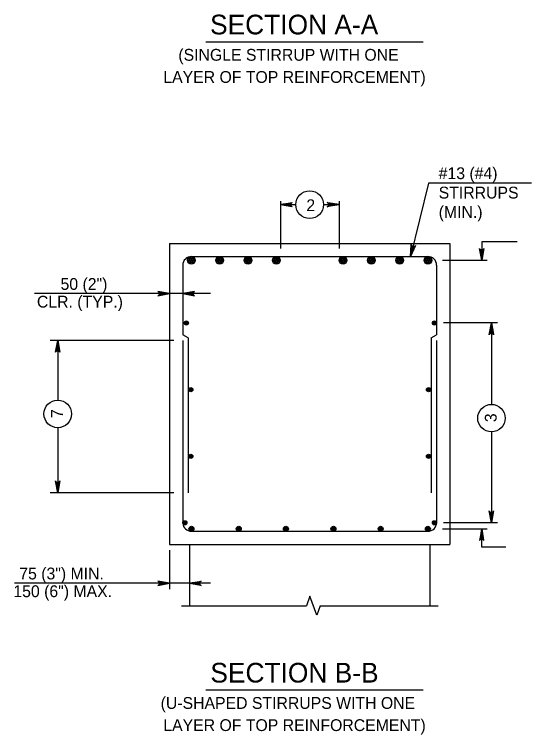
# Model space of a CAD drawing. Extents: x 646165 to 651486, y 296916 to 299292.
# Drawn here: x 647939.7 to 648071, y 298263.1 to 298446.1 of the extents above; entities that cross this region are included whole.
import ezdxf

# ---------------------------------------------------------------- set-up
doc = ezdxf.new("R2010")
doc.units = 0
for name, color, linetype in [('51', 7, 'Continuous'), ('52', 7, 'Continuous'), ('53', 7, 'Continuous'), ('54', 7, 'Continuous')]:
    doc.layers.add(name, color=color, linetype=linetype)

msp = doc.modelspace()

# ---------------------------------------------------------------- linework, layer by layer
at = {"layer": '51'}
for p, q in [((647979.08, 298387.9), (647979.08, 298311.43)), ((647979.08, 298387.9), (648050.2, 298387.9)), ((648050.2, 298387.9), (648050.2, 298311.43)), ((647979.08, 298311.43), (648050.2, 298311.43)), ((647984.08, 298311.43), (647984.08, 298295.85)), ((648045.2, 298311.43), (648045.2, 298295.85))]:
    msp.add_line(p, q, dxfattribs=at)
at = {"layer": '52'}
for p, q in [((648044.79, 298403.22), (648040.28, 298384.57)), ((648071.01, 298403.22), (648044.79, 298403.22)), ((648007.21, 298398.59), (648007.21, 298386.58)), ((648022.1, 298398.59), (648022.1, 298386.58)), ((648007.21, 298397.74), (648011.14, 298397.74)), ((648018.14, 298397.74), (648022.1, 298397.74)), ((648067.31, 298388.27), (648058.35, 298388.27)), ((648058.35, 298388.27), (648058.35, 298383.6)), ((648048.39, 298383.6), (648059.68, 298383.6)), ((647989.47, 298375.15), (647944.78, 298375.15)), ((648062.36, 298367.68), (648048.63, 298367.68)), ((648060.81, 298367.68), (648060.81, 298347.01)), ((647980.12, 298363.23), (647948.71, 298363.23)), ((647950.65, 298363.23), (647950.65, 298348.07)), ((647950.65, 298341.07), (647950.65, 298324.57)), ((648060.81, 298340.01), (648060.81, 298316.93)), ((647980.12, 298324.57), (647948.71, 298324.57)), ((648062.36, 298316.93), (648048.63, 298316.93)), ((648048.39, 298315.4), (648059.68, 298315.4)), ((648058.35, 298310.73), (648058.35, 298315.4)), ((648064.49, 298310.73), (648058.35, 298310.73)), ((647979.08, 298309.95), (647979.08, 298300.07)), ((647989.47, 298301.55), (647939.65, 298301.55)), ((647982.11, 298295.85), (648013.8, 298295.85)), ((648017.3, 298295.85), (648047.27, 298295.85))]:
    msp.add_line(p, q, dxfattribs=at)
for points in [[(648007.21, 298397.74), (648010.19, 298398.3), (648010.08, 298398.22), (648009.96, 298398.14), (648009.9, 298398.04), (648009.84, 298397.94), (648009.82, 298397.84), (648009.81, 298397.74), (648009.82, 298397.64), (648009.84, 298397.54), (648009.9, 298397.44), (648009.96, 298397.34), (648010.08, 298397.26), (648010.19, 298397.18), (648007.21, 298397.74), (648010.08, 298397.26), (648009.96, 298397.34), (648007.21, 298397.74), (648009.9, 298397.44), (648009.84, 298397.54), (648007.21, 298397.74), (648009.82, 298397.64), (648009.81, 298397.74), (648007.21, 298397.74), (648009.82, 298397.84), (648009.84, 298397.94), (648007.21, 298397.74), (648009.9, 298398.04), (648009.96, 298398.14), (648007.21, 298397.74), (648010.08, 298398.22)], [(648022.1, 298397.74), (648019.12, 298397.18), (648019.23, 298397.26), (648019.35, 298397.34), (648019.41, 298397.44), (648019.46, 298397.54), (648019.48, 298397.64), (648019.5, 298397.74), (648019.48, 298397.84), (648019.46, 298397.94), (648019.41, 298398.04), (648019.35, 298398.14), (648019.23, 298398.22), (648019.12, 298398.3), (648022.1, 298397.74), (648019.23, 298398.22), (648019.35, 298398.14), (648022.1, 298397.74), (648019.41, 298398.04), (648019.46, 298397.94), (648022.1, 298397.74), (648019.48, 298397.84), (648019.5, 298397.74), (648022.1, 298397.74), (648019.48, 298397.64), (648019.46, 298397.54), (648022.1, 298397.74), (648019.41, 298397.44), (648019.35, 298397.34), (648022.1, 298397.74), (648019.23, 298397.26)], [(648040.28, 298384.57), (648040.44, 298387.6), (648040.49, 298387.47), (648040.54, 298387.34), (648040.62, 298387.26), (648040.7, 298387.17), (648040.8, 298387.13), (648040.89, 298387.09), (648040.99, 298387.09), (648041.09, 298387.08), (648041.2, 298387.11), (648041.31, 298387.15), (648041.42, 298387.24), (648041.52, 298387.33), (648040.28, 298384.57), (648041.42, 298387.24), (648041.31, 298387.15), (648040.28, 298384.57), (648041.2, 298387.11), (648041.09, 298387.08), (648040.28, 298384.57), (648040.99, 298387.09), (648040.89, 298387.09), (648040.28, 298384.57), (648040.8, 298387.13), (648040.7, 298387.17), (648040.28, 298384.57), (648040.62, 298387.26), (648040.54, 298387.34), (648040.28, 298384.57), (648040.49, 298387.47)], [(648058.35, 298383.6), (648057.79, 298386.58), (648057.87, 298386.47), (648057.95, 298386.35), (648058.05, 298386.29), (648058.15, 298386.23), (648058.25, 298386.22), (648058.35, 298386.2), (648058.45, 298386.22), (648058.55, 298386.23), (648058.65, 298386.29), (648058.75, 298386.35), (648058.83, 298386.47), (648058.91, 298386.58), (648058.35, 298383.6), (648058.83, 298386.47), (648058.75, 298386.35), (648058.35, 298383.6), (648058.65, 298386.29), (648058.55, 298386.23), (648058.35, 298383.6), (648058.45, 298386.22), (648058.35, 298386.2), (648058.35, 298383.6), (648058.25, 298386.22), (648058.15, 298386.23), (648058.35, 298383.6), (648058.05, 298386.29), (648057.95, 298386.35), (648058.35, 298383.6), (648057.87, 298386.47)], [(647979.08, 298375.15), (647976.1, 298375.71), (647976.21, 298375.63), (647976.33, 298375.55), (647976.39, 298375.45), (647976.45, 298375.35), (647976.47, 298375.25), (647976.48, 298375.15), (647976.47, 298375.05), (647976.45, 298374.95), (647976.39, 298374.85), (647976.33, 298374.75), (647976.21, 298374.68), (647976.1, 298374.6), (647979.08, 298375.15), (647976.21, 298374.68), (647976.33, 298374.75), (647979.08, 298375.15), (647976.39, 298374.85), (647976.45, 298374.95), (647979.08, 298375.15), (647976.47, 298375.05), (647976.48, 298375.15), (647979.08, 298375.15), (647976.47, 298375.25), (647976.45, 298375.35), (647979.08, 298375.15), (647976.39, 298375.45), (647976.33, 298375.55), (647979.08, 298375.15), (647976.21, 298375.63)], [(647982.42, 298375.15), (647985.4, 298374.6), (647985.28, 298374.68), (647985.17, 298374.75), (647985.11, 298374.85), (647985.05, 298374.95), (647985.03, 298375.05), (647985.02, 298375.15), (647985.03, 298375.25), (647985.05, 298375.35), (647985.11, 298375.45), (647985.17, 298375.55), (647985.28, 298375.63), (647985.4, 298375.71), (647982.42, 298375.15), (647985.28, 298375.63), (647985.17, 298375.55), (647982.42, 298375.15), (647985.11, 298375.45), (647985.05, 298375.35), (647982.42, 298375.15), (647985.03, 298375.25), (647985.02, 298375.15), (647982.42, 298375.15), (647985.03, 298375.05), (647985.05, 298374.95), (647982.42, 298375.15), (647985.11, 298374.85), (647985.17, 298374.75), (647982.42, 298375.15), (647985.28, 298374.68)], [(648060.81, 298367.68), (648061.37, 298364.7), (648061.29, 298364.81), (648061.21, 298364.93), (648061.11, 298364.99), (648061.01, 298365.05), (648060.91, 298365.06), (648060.81, 298365.08), (648060.71, 298365.06), (648060.61, 298365.05), (648060.51, 298364.99), (648060.41, 298364.93), (648060.33, 298364.81), (648060.25, 298364.7), (648060.81, 298367.68), (648060.33, 298364.81), (648060.41, 298364.93), (648060.81, 298367.68), (648060.51, 298364.99), (648060.61, 298365.05), (648060.81, 298367.68), (648060.71, 298365.06), (648060.81, 298365.08), (648060.81, 298367.68), (648060.91, 298365.06), (648061.01, 298365.05), (648060.81, 298367.68), (648061.11, 298364.99), (648061.21, 298364.93), (648060.81, 298367.68), (648061.29, 298364.81)], [(647950.65, 298363.23), (647951.21, 298360.25), (647951.13, 298360.37), (647951.05, 298360.48), (647950.95, 298360.54), (647950.85, 298360.6), (647950.75, 298360.62), (647950.65, 298360.63), (647950.55, 298360.62), (647950.45, 298360.6), (647950.35, 298360.54), (647950.25, 298360.48), (647950.17, 298360.37), (647950.09, 298360.25), (647950.65, 298363.23), (647950.17, 298360.37), (647950.25, 298360.48), (647950.65, 298363.23), (647950.35, 298360.54), (647950.45, 298360.6), (647950.65, 298363.23), (647950.55, 298360.62), (647950.65, 298360.63), (647950.65, 298363.23), (647950.75, 298360.62), (647950.85, 298360.6), (647950.65, 298363.23), (647950.95, 298360.54), (647951.05, 298360.48), (647950.65, 298363.23), (647951.13, 298360.37)], [(647950.65, 298324.57), (647950.09, 298327.55), (647950.17, 298327.43), (647950.25, 298327.32), (647950.35, 298327.26), (647950.45, 298327.2), (647950.55, 298327.18), (647950.65, 298327.17), (647950.75, 298327.18), (647950.85, 298327.2), (647950.95, 298327.26), (647951.05, 298327.32), (647951.13, 298327.43), (647951.21, 298327.55), (647950.65, 298324.57), (647951.13, 298327.43), (647951.05, 298327.32), (647950.65, 298324.57), (647950.95, 298327.26), (647950.85, 298327.2), (647950.65, 298324.57), (647950.75, 298327.18), (647950.65, 298327.17), (647950.65, 298324.57), (647950.55, 298327.18), (647950.45, 298327.2), (647950.65, 298324.57), (647950.35, 298327.26), (647950.25, 298327.32), (647950.65, 298324.57), (647950.17, 298327.43)], [(648060.81, 298316.93), (648060.25, 298319.92), (648060.33, 298319.8), (648060.41, 298319.69), (648060.51, 298319.63), (648060.61, 298319.57), (648060.71, 298319.55), (648060.81, 298319.53), (648060.91, 298319.55), (648061.01, 298319.57), (648061.11, 298319.63), (648061.21, 298319.69), (648061.29, 298319.8), (648061.37, 298319.92), (648060.81, 298316.93), (648061.29, 298319.8), (648061.21, 298319.69), (648060.81, 298316.93), (648061.11, 298319.63), (648061.01, 298319.57), (648060.81, 298316.93), (648060.91, 298319.55), (648060.81, 298319.53), (648060.81, 298316.93), (648060.71, 298319.55), (648060.61, 298319.57), (648060.81, 298316.93), (648060.51, 298319.63), (648060.41, 298319.69), (648060.81, 298316.93), (648060.33, 298319.8)], [(648058.35, 298315.4), (648057.79, 298312.42), (648057.87, 298312.53), (648057.95, 298312.65), (648058.05, 298312.71), (648058.15, 298312.77), (648058.25, 298312.78), (648058.35, 298312.8), (648058.45, 298312.78), (648058.55, 298312.77), (648058.65, 298312.71), (648058.75, 298312.65), (648058.83, 298312.53), (648058.91, 298312.42), (648058.35, 298315.4), (648058.83, 298312.53), (648058.75, 298312.65), (648058.35, 298315.4), (648058.65, 298312.71), (648058.55, 298312.77), (648058.35, 298315.4), (648058.45, 298312.78), (648058.35, 298312.8), (648058.35, 298315.4), (648058.25, 298312.78), (648058.15, 298312.77), (648058.35, 298315.4), (648058.05, 298312.71), (648057.95, 298312.65), (648058.35, 298315.4), (648057.87, 298312.53)], [(647979.08, 298301.55), (647976.1, 298302.11), (647976.21, 298302.03), (647976.33, 298301.95), (647976.39, 298301.85), (647976.45, 298301.75), (647976.47, 298301.65), (647976.48, 298301.55), (647976.47, 298301.45), (647976.45, 298301.35), (647976.39, 298301.25), (647976.33, 298301.15), (647976.21, 298301.07), (647976.1, 298300.99), (647979.08, 298301.55), (647976.21, 298301.07), (647976.33, 298301.15), (647979.08, 298301.55), (647976.39, 298301.25), (647976.45, 298301.35), (647979.08, 298301.55), (647976.47, 298301.45), (647976.48, 298301.55), (647979.08, 298301.55), (647976.47, 298301.65), (647976.45, 298301.75), (647979.08, 298301.55), (647976.39, 298301.85), (647976.33, 298301.95), (647979.08, 298301.55), (647976.21, 298302.03)], [(647984.08, 298301.55), (647987.07, 298302.11), (647986.95, 298302.03), (647986.84, 298301.95), (647986.78, 298301.85), (647986.72, 298301.75), (647986.7, 298301.65), (647986.68, 298301.55), (647986.7, 298301.45), (647986.72, 298301.35), (647986.78, 298301.25), (647986.84, 298301.15), (647986.95, 298301.07), (647987.07, 298300.99), (647984.08, 298301.55), (647986.95, 298301.07), (647986.84, 298301.15), (647984.08, 298301.55), (647986.78, 298301.25), (647986.72, 298301.35), (647984.08, 298301.55), (647986.7, 298301.45), (647986.68, 298301.55), (647984.08, 298301.55), (647986.7, 298301.65), (647986.72, 298301.75), (647984.08, 298301.55), (647986.78, 298301.85), (647986.84, 298301.95), (647984.08, 298301.55), (647986.95, 298302.03)], [(648017.3, 298295.85), (648016.43, 298293.45), (648014.68, 298298.25), (648013.8, 298295.85)]]:
    msp.add_lwpolyline(points, dxfattribs=at)
for centre in [(648014.64, 298397.74), (647950.65, 298344.57), (648060.81, 298343.51)]:
    msp.add_circle(centre, 3.5, dxfattribs=at)
at = {"layer": '53'}
for p, q in [((647988.25, 298439.14), (648043.46, 298439.14)), ((647988.25, 298274.49), (648043.46, 298274.49))]:
    msp.add_line(p, q, dxfattribs=at)
at = {"layer": '54'}
for p, q in [((647984.62, 298384.57), (648044.67, 298384.57)), ((647982.42, 298382.37), (647982.42, 298364.67)), ((648046.87, 298382.37), (648046.87, 298364.67)), ((647983.75, 298363.9), (647982.42, 298364.67)), ((647983.75, 298363.9), (647983.75, 298324.57)), ((648045.54, 298363.9), (648046.87, 298364.67)), ((648045.54, 298363.9), (648045.54, 298324.57)), ((647982.42, 298363.23), (647982.42, 298316.83)), ((648046.87, 298363.23), (648046.87, 298316.97)), ((647984.62, 298314.77), (648044.67, 298314.77))]:
    msp.add_line(p, q, dxfattribs=at)
for centre, radius in [((647984.62, 298383.6), 0.967), ((647984.62, 298383.6), 0.725), ((647984.62, 298383.6), 0.483), ((647984.62, 298383.6), 0.242), ((647991.78, 298383.6), 0.967), ((647991.78, 298383.6), 0.725), ((647991.78, 298383.6), 0.483), ((647991.78, 298383.6), 0.242), ((647998.98, 298383.6), 0.967), ((647998.98, 298383.6), 0.725), ((647998.98, 298383.6), 0.483), ((647998.98, 298383.6), 0.242), ((648006.18, 298383.6), 0.967), ((648006.18, 298383.6), 0.725), ((648006.18, 298383.6), 0.483), ((648006.18, 298383.6), 0.242), ((648023.11, 298383.6), 0.967), ((648023.11, 298383.6), 0.725), ((648023.11, 298383.6), 0.483), ((648023.11, 298383.6), 0.242), ((648030.31, 298383.6), 0.967), ((648030.31, 298383.6), 0.725), ((648030.31, 298383.6), 0.483), ((648030.31, 298383.6), 0.242), ((648037.51, 298383.6), 0.967), ((648037.51, 298383.6), 0.725), ((648037.51, 298383.6), 0.483), ((648037.51, 298383.6), 0.242), ((648044.67, 298383.6), 0.967), ((648044.67, 298383.6), 0.725), ((648044.67, 298383.6), 0.483), ((648044.67, 298383.6), 0.242), ((647983.32, 298367.68), 0.533), ((647983.32, 298367.68), 0.4), ((647983.32, 298367.68), 0.267), ((647983.32, 298367.68), 0.133), ((648046.34, 298367.68), 0.533), ((648046.34, 298367.68), 0.4), ((648046.34, 298367.68), 0.267), ((648046.34, 298367.68), 0.133), ((647984.44, 298350.75), 0.533), ((647984.44, 298350.75), 0.4), ((647984.44, 298350.75), 0.267), ((647984.44, 298350.75), 0.133), ((648044.84, 298350.75), 0.533), ((648044.84, 298350.75), 0.4), ((648044.84, 298350.75), 0.267), ((648044.84, 298350.75), 0.133), ((647984.44, 298333.81), 0.533), ((647984.44, 298333.81), 0.4), ((647984.44, 298333.81), 0.267), ((648044.84, 298333.81), 0.533), ((648044.84, 298333.81), 0.4), ((648044.84, 298333.81), 0.267), ((647984.44, 298333.81), 0.133), ((648044.84, 298333.81), 0.133), ((647982.95, 298316.93), 0.533), ((647982.95, 298316.93), 0.4), ((647982.95, 298316.93), 0.267), ((647982.95, 298316.93), 0.133), ((647984.62, 298315.4), 0.633), ((647984.62, 298315.4), 0.475), ((647996.62, 298315.4), 0.633), ((647996.62, 298315.4), 0.475), ((648008.62, 298315.4), 0.633), ((648008.62, 298315.4), 0.475), ((648020.67, 298315.4), 0.633), ((648020.67, 298315.4), 0.475), ((648032.67, 298315.4), 0.633), ((648032.67, 298315.4), 0.475), ((648044.67, 298315.4), 0.633), ((648044.67, 298315.4), 0.475), ((648046.34, 298316.93), 0.533), ((648046.34, 298316.93), 0.4), ((648046.34, 298316.93), 0.267), ((648046.34, 298316.93), 0.133), ((647984.62, 298315.4), 0.317), ((647984.62, 298315.4), 0.158), ((647996.62, 298315.4), 0.317), ((647996.62, 298315.4), 0.158), ((648008.62, 298315.4), 0.317), ((648008.62, 298315.4), 0.158), ((648020.67, 298315.4), 0.317), ((648020.67, 298315.4), 0.158), ((648032.67, 298315.4), 0.317), ((648032.67, 298315.4), 0.158), ((648044.67, 298315.4), 0.317), ((648044.67, 298315.4), 0.158)]:
    msp.add_circle(centre, radius, dxfattribs=at)
for centre, start, end in [((647984.62, 298382.37), 90, 180), ((648044.67, 298382.37), 0, 90), ((647984.62, 298316.97), 183.5466, 269.9991), ((648044.67, 298316.97), 270, 0)]:
    msp.add_arc(centre, 2.2, start, end, dxfattribs=at)

# ---------------------------------------------------------------- texts
at = {"layer": '53'}
for s, height, p in [('SECTION A-A', 5, (647989.34, 298440.99)), ('(SINGLE STIRRUP WITH ONE', 3, (647981.29, 298434.3)), ('LAYER OF TOP REINFORCEMENT)', 3, (647977.47, 298428.67)), ('#13 (#4)', 3, (648047.41, 298404.22)), ('STIRRUPS', 3, (648047.41, 298399.3)), ('2', 3, (648013.8, 298396.09)), ('(MIN.)', 3, (648047.41, 298394.38)), ('50 (2")', 3, (647951.37, 298376.09)), ('CLR. (TYP.)', 3, (647945.37, 298371.59)), ('75 (3") MIN.', 3, (647940.89, 298302.54)), ('150 (6") MAX.', 3, (647939.39, 298298.04)), ('SECTION B-B', 5, (647989.42, 298276.34)), ('(U-SHAPED STIRRUPS WITH ONE', 3, (647976.79, 298269.65)), ('LAYER OF TOP REINFORCEMENT)', 3, (647977.47, 298264.02))]:
    msp.add_text(s, height=height, dxfattribs=at).set_placement(p)
for s, p in [('7', (647951.98, 298343.54)), ('3', (648062.13, 298342.49))]:
    msp.add_text(s, height=3, rotation=90, dxfattribs=at).set_placement(p)

doc.saveas('drawing.dxf')
